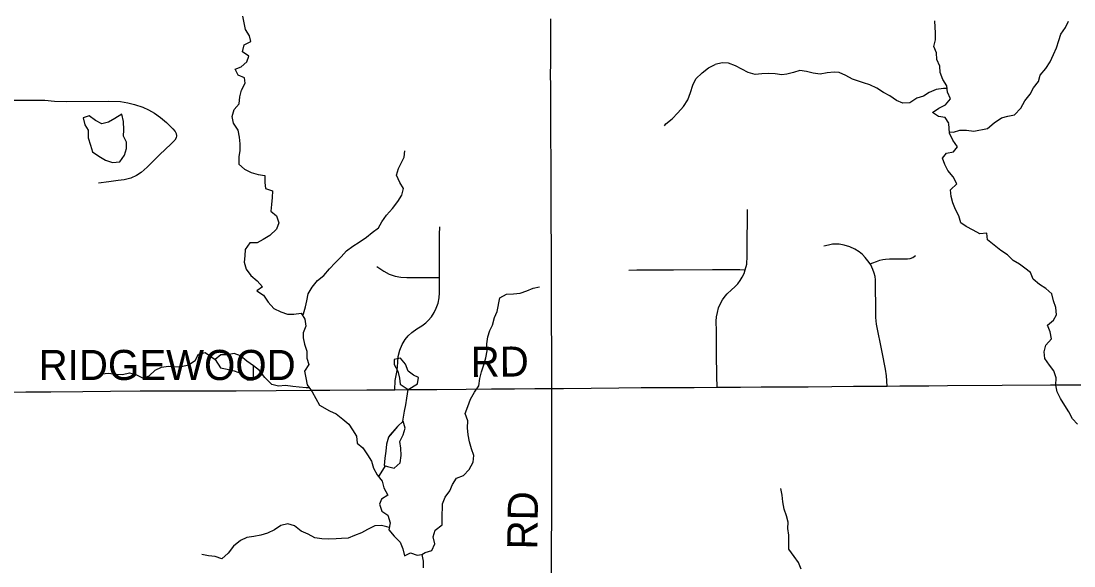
# Model space of a CAD drawing. Extents: x 0 to 34, y 0 to 22.
# Drawn here: x 6.998 to 7.992, y 14.845 to 15.36 of the extents above; entities that cross this region are included whole.
import ezdxf

# ---------------------------------------------------------------- set-up
doc = ezdxf.new("R2010")
doc.units = 0
for name, color, linetype in [('GM_X_County_Road', 7, 'Continuous'), ('GM_X_County_Road_Text', 7, 'Continuous'), ('GM_X_Minor_Lake', 7, 'Continuous'), ('GM_X_Minor_River', 7, 'Continuous'), ('GM_X_Township_Road', 7, 'Continuous'), ('GM_X_Township_Road_Text', 7, 'Continuous')]:
    doc.layers.add(name, color=color, linetype=linetype)

msp = doc.modelspace()

# ---------------------------------------------------------------- linework, layer by layer
at = {"layer": 'GM_X_County_Road'}
msp.add_lwpolyline([(6.98496, 15.00949), (7.00223, 15.00972), (7.02584, 15.00993), (7.05596, 15.01022), (7.08206, 15.0104), (7.11021, 15.01066), (7.20092, 15.01086), (7.23849, 15.01115), (7.27122, 15.01144), (7.28915, 15.01135), (7.32399, 15.01164), (7.3507, 15.01181), (7.36491, 15.01193), (7.39034, 15.01199), (7.41797, 15.01228), (7.44175, 15.0126), (7.46342, 15.0128), (7.48288, 15.01286), (7.4953, 15.01301), (7.49888, 15.01296), (7.50974, 15.01303), (7.536, 15.01332), (7.56212, 15.01352), (7.58306, 15.01376), (7.60788, 15.0139), (7.63299, 15.01405), (7.65484, 15.0142), (7.67693, 15.01437), (7.69654, 15.01457), (7.74068, 15.01468), (7.76315, 15.01483), (7.78369, 15.01503), (7.80642, 15.01518), (7.81548, 15.0152), (7.82718, 15.01534), (7.85482, 15.01561), (7.8722, 15.01579), (7.92384, 15.01606), (7.96966, 15.01632), (8.02509, 15.01647)], dxfattribs=at)
at = {"layer": 'GM_X_Minor_Lake'}
for points in [[(7.09463, 15.25704), (7.09448, 15.26508), (7.09285, 15.27188), (7.08629, 15.26797), (7.08012, 15.26445), (7.07409, 15.26283), (7.06798, 15.26595), (7.06205, 15.27021), (7.05621, 15.26859), (7.05784, 15.26178), (7.06104, 15.25679)], [(7.06104, 15.25679), (7.06094, 15.2559), (7.06116, 15.24945), (7.06327, 15.24282), (7.06519, 15.23639), (7.07126, 15.23243), (7.07752, 15.22848), (7.08416, 15.22623), (7.09097, 15.22683), (7.09549, 15.23329), (7.09717, 15.23956), (7.09714, 15.24544), (7.09428, 15.2513), (7.09463, 15.25705)], [(7.06104, 15.25679), (7.06094, 15.2559), (7.06116, 15.24945), (7.06327, 15.24282), (7.06519, 15.23639), (7.07126, 15.23243), (7.07752, 15.22848), (7.08416, 15.22623), (7.09097, 15.22683), (7.09549, 15.23329), (7.09717, 15.23956), (7.09714, 15.24544), (7.09428, 15.2513), (7.09463, 15.25704)], [(7.18087, 15.04041), (7.18587, 15.03254), (7.19235, 15.03114), (7.19901, 15.02975), (7.2057, 15.02702), (7.21112, 15.02124), (7.21719, 15.02117), (7.21712, 15.02887)], [(7.21712, 15.02887), (7.21714, 15.03426), (7.21079, 15.03888), (7.20482, 15.04389), (7.1989, 15.04606), (7.19247, 15.0448), (7.1864, 15.04488), (7.18089, 15.04039)], [(7.18089, 15.04039), (7.18587, 15.03254), (7.19235, 15.03114), (7.19901, 15.02975), (7.2057, 15.02702), (7.21112, 15.02124), (7.21719, 15.02117), (7.21712, 15.02887)], [(7.21723, 15.02887), (7.21714, 15.03426), (7.21079, 15.03888), (7.20482, 15.04389), (7.1989, 15.04606), (7.19247, 15.0448), (7.1864, 15.04488), (7.18092, 15.04041)], [(7.35272, 15.04093), (7.34978, 15.04034), (7.34987, 15.03559), (7.3534, 15.0294), (7.35504, 15.02279), (7.35553, 15.01691), (7.36321, 15.01213)], [(7.35272, 15.04093), (7.34978, 15.04034), (7.34987, 15.03559), (7.3534, 15.0294), (7.35504, 15.02279), (7.35553, 15.01691), (7.36322, 15.01212)], [(7.36321, 15.01213), (7.37202, 15.01722), (7.37305, 15.0235), (7.36827, 15.0255), (7.36307, 15.02939), (7.36049, 15.03598), (7.35602, 15.04159), (7.35272, 15.04093)], [(7.36323, 15.01214), (7.37202, 15.01722), (7.37305, 15.0235), (7.36827, 15.0255), (7.36307, 15.02939), (7.36049, 15.03598), (7.35602, 15.04159), (7.3528, 15.0409)], [(7.34038, 14.94023), (7.34351, 14.93946), (7.34999, 14.93769), (7.35558, 14.94292), (7.35659, 14.94977), (7.35608, 14.95659), (7.35521, 14.96302), (7.3585, 14.96934), (7.36028, 14.97564), (7.35827, 14.98205), (7.35323, 14.97721), (7.34605, 14.96901)], [(7.34038, 14.94023), (7.34351, 14.93946), (7.34999, 14.93769), (7.35558, 14.94292), (7.35659, 14.94977), (7.35608, 14.95659), (7.35521, 14.96302), (7.3585, 14.96934), (7.36028, 14.97564), (7.35827, 14.98205), (7.35323, 14.97721), (7.34599, 14.96894)], [(7.34605, 14.96901), (7.3447, 14.967), (7.34274, 14.96032), (7.3421, 14.95386), (7.34109, 14.9472), (7.34038, 14.94023)], [(7.34599, 14.96892), (7.3447, 14.967), (7.34274, 14.96032), (7.3421, 14.95386), (7.34109, 14.9472), (7.34038, 14.94022)]]:
    msp.add_lwpolyline(points, dxfattribs=at)
at = {"layer": 'GM_X_Minor_River'}
for points in [[(7.20187, 15.25785), (7.19815, 15.26329), (7.1969, 15.26972), (7.19887, 15.2764), (7.2035, 15.28179), (7.20414, 15.28844), (7.20592, 15.29473), (7.20921, 15.30105), (7.20874, 15.30636), (7.20265, 15.30872), (7.19971, 15.31436), (7.20553, 15.31674), (7.21075, 15.32138), (7.21273, 15.32673), (7.20661, 15.3308), (7.20838, 15.33747), (7.21476, 15.34043), (7.21334, 15.3459), (7.20945, 15.35191), (7.20821, 15.35815), (7.20696, 15.36458)], [(7.87372, 15.26329), (7.86996, 15.26888), (7.86387, 15.26982), (7.85816, 15.27343), (7.86424, 15.27762), (7.87033, 15.28067), (7.87507, 15.28657), (7.87221, 15.29284), (7.87163, 15.29873), (7.86801, 15.30462), (7.86553, 15.31128), (7.86495, 15.31736), (7.86227, 15.32363), (7.86188, 15.32972), (7.8594, 15.3358), (7.86111, 15.34227), (7.86091, 15.34835), (7.86047, 15.35996)], [(7.91631, 15.26364), (7.92323, 15.26837), (7.92913, 15.2699), (7.93559, 15.27124), (7.94148, 15.27753), (7.94528, 15.28437), (7.95021, 15.29085), (7.95344, 15.29675), (7.95819, 15.30265), (7.95989, 15.30873), (7.96502, 15.31501), (7.96919, 15.32148), (7.97223, 15.32833), (7.97526, 15.33461), (7.97734, 15.34146), (7.97924, 15.34755), (7.98379, 15.35364), (7.98664, 15.35973)], [(7.60501, 15.2609), (7.60648, 15.26285), (7.61226, 15.26769), (7.61784, 15.2731), (7.62322, 15.27927), (7.62727, 15.2856), (7.62979, 15.29247), (7.63175, 15.29934), (7.63487, 15.30527), (7.64063, 15.31088), (7.6466, 15.31573), (7.65297, 15.3188)], [(7.8719, 15.29602), (7.8684, 15.29626), (7.86156, 15.29511), (7.85509, 15.29225), (7.84958, 15.28901), (7.8433, 15.2871), (7.83665, 15.28253), (7.83018, 15.28233), (7.82409, 15.2848), (7.818, 15.28916), (7.81191, 15.29239), (7.80562, 15.29656), (7.79896, 15.2996), (7.79306, 15.30149), (7.7883, 15.303), (7.78259, 15.3049), (7.77631, 15.3085), (7.77003, 15.31135), (7.76527, 15.31153), (7.7588, 15.31095), (7.75196, 15.30961), (7.74549, 15.31056), (7.73921, 15.31226), (7.73293, 15.3132), (7.72703, 15.31129), (7.72057, 15.30957), (7.71581, 15.30919), (7.70972, 15.30994), (7.70364, 15.31031), (7.69717, 15.30993), (7.6907, 15.30935), (7.68423, 15.31124), (7.67814, 15.31447), (7.67204, 15.3175), (7.66557, 15.31997), (7.65948, 15.32053), (7.65297, 15.31877)], [(7.20186, 15.25786), (7.20236, 15.25688), (7.20371, 15.25025), (7.20431, 15.24381), (7.20414, 15.23774), (7.20322, 15.23167), (7.20325, 15.22485), (7.20876, 15.21994), (7.21483, 15.21693), (7.22165, 15.21488), (7.2279, 15.21396), (7.22774, 15.20732), (7.22852, 15.20164), (7.23497, 15.19958), (7.2348, 15.19313), (7.23426, 15.18668), (7.23353, 15.18042), (7.23885, 15.1759), (7.24115, 15.16946), (7.23871, 15.16338), (7.23249, 15.15748), (7.22626, 15.15347), (7.22059, 15.15041), (7.21377, 15.15057), (7.20926, 15.1443), (7.2089, 15.13823), (7.20836, 15.13235), (7.21028, 15.12572), (7.21466, 15.11948), (7.22055, 15.11458), (7.22549, 15.10891), (7.2204, 15.10529), (7.22647, 15.10095), (7.23104, 15.09434), (7.23618, 15.08848), (7.24301, 15.08529), (7.24926, 15.08323), (7.25532, 15.08307), (7.26213, 15.08404), (7.26556, 15.07837), (7.26654, 15.07193), (7.26391, 15.06566), (7.26412, 15.06073), (7.26528, 15.05486), (7.26758, 15.04805), (7.26742, 15.0416), (7.26952, 15.03554), (7.26519, 15.02927), (7.26655, 15.02302), (7.26771, 15.01657), (7.27266, 15.00996), (7.2759, 15.00353), (7.27952, 14.99729), (7.28901, 14.99202), (7.29508, 14.98901), (7.30154, 14.98392), (7.30705, 14.9792), (7.31048, 14.97391), (7.31429, 14.96786), (7.31489, 14.96123), (7.3202, 14.95689), (7.32477, 14.95046), (7.32858, 14.94441), (7.33031, 14.93778), (7.33394, 14.93154), (7.33869, 14.9255), (7.34005, 14.91906), (7.34386, 14.91225), (7.33782, 14.90862), (7.33594, 14.90368), (7.33824, 14.89725), (7.34394, 14.89329), (7.34624, 14.88628), (7.34475, 14.87945), (7.35008, 14.8736), (7.35559, 14.86793), (7.35808, 14.86169), (7.35962, 14.85506), (7.36548, 14.85774), (7.37173, 14.85549)], [(7.99518, 14.97919), (7.99037, 14.98446), (7.98688, 14.99089), (7.9832, 14.99694), (7.97914, 15.00355), (7.97584, 15.00979), (7.97462, 15.01625), (7.97493, 15.0231), (7.97258, 15.02954), (7.96852, 15.03501), (7.96408, 15.04143), (7.96344, 15.04751), (7.96508, 15.05381), (7.97053, 15.05977), (7.96912, 15.0666), (7.96658, 15.07266), (7.97242, 15.07749), (7.97521, 15.08266), (7.97457, 15.08931), (7.97241, 15.09575), (7.97081, 15.1022), (7.96524, 15.10747), (7.95912, 15.1112), (7.95317, 15.11608), (7.95082, 15.12253), (7.94526, 15.12646), (7.94028, 15.13021), (7.93416, 15.13375), (7.92897, 15.13902), (7.92265, 15.14333), (7.91651, 15.14839), (7.91018, 15.15327), (7.90935, 15.15973), (7.90289, 15.15909), (7.89639, 15.16244), (7.89008, 15.16598), (7.88491, 15.16935), (7.88294, 15.17598), (7.87983, 15.18204), (7.87748, 15.18829), (7.87589, 15.19436), (7.87525, 15.20044), (7.88108, 15.20621), (7.87778, 15.21265), (7.87258, 15.21868), (7.86966, 15.22435), (7.86751, 15.23041), (7.87144, 15.23522), (7.87789, 15.23624), (7.88164, 15.24104), (7.87739, 15.24746), (7.87409, 15.25389), (7.87367, 15.26327)], [(7.87401, 15.25514), (7.87787, 15.25508), (7.88394, 15.25686), (7.8904, 15.25693), (7.89725, 15.25587), (7.91015, 15.2583), (7.91633, 15.26364)], [(7.26307, 15.08249), (7.26441, 15.0833), (7.26627, 15.08994), (7.26739, 15.09582), (7.26887, 15.10227), (7.27244, 15.10855), (7.27753, 15.11482), (7.28338, 15.11959), (7.28884, 15.12587), (7.29412, 15.13158), (7.29997, 15.13729), (7.30506, 15.14281), (7.31091, 15.14739), (7.31695, 15.15102), (7.32375, 15.15597), (7.32922, 15.16017), (7.33526, 15.16455), (7.33826, 15.17044), (7.34278, 15.17653), (7.34825, 15.18281), (7.35352, 15.18947), (7.35709, 15.19555), (7.35877, 15.20162), (7.35534, 15.20749), (7.3521, 15.2143), (7.35415, 15.22057), (7.35697, 15.22645), (7.35922, 15.2312), (7.36014, 15.23746)], [(7.37608, 14.85627), (7.37929, 14.85813), (7.38554, 14.85993), (7.3883, 14.86643), (7.38688, 14.87287), (7.3885, 14.87917), (7.39509, 14.8842), (7.39538, 14.89029), (7.39557, 14.90397), (7.39814, 14.91028), (7.40243, 14.91623), (7.40501, 14.92235), (7.40892, 14.9283), (7.41535, 14.93086), (7.42059, 14.93664), (7.42449, 14.94354), (7.42516, 14.94982), (7.42298, 14.95606), (7.42099, 14.96249), (7.41994, 14.96931), (7.41927, 14.97595), (7.41956, 14.98242), (7.41699, 14.98922), (7.41937, 14.99609), (7.42212, 15.00298), (7.42564, 15.00949), (7.42993, 15.01563), (7.43079, 15.02229), (7.4324, 15.02878), (7.4346, 15.03527), (7.43659, 15.04195), (7.43783, 15.04843), (7.43754, 15.05526), (7.43821, 15.06173), (7.44022, 15.06784), (7.44262, 15.07282), (7.44461, 15.07988), (7.44719, 15.08562), (7.44967, 15.09857), (7.45609, 15.1019), (7.46256, 15.10218), (7.46902, 15.10285), (7.47507, 15.10522), (7.48112, 15.10778), (7.48719, 15.10881)], [(7.0738, 15.02674), (7.08024, 15.02733), (7.08725, 15.02642), (7.09349, 15.02625), (7.09993, 15.02761), (7.10656, 15.02574), (7.11282, 15.02273), (7.11868, 15.02484), (7.12434, 15.03037), (7.13038, 15.03324), (7.13682, 15.03402), (7.1425, 15.03348), (7.14931, 15.0337), (7.15574, 15.03543), (7.16197, 15.03944), (7.16517, 15.04552), (7.1716, 15.04687), (7.18087, 15.04044)], [(7.27, 15.01351), (7.26696, 15.01354), (7.26033, 15.01408), (7.25427, 15.01481), (7.24745, 15.01573), (7.24064, 15.01513), (7.23439, 15.01681), (7.22773, 15.02323), (7.22278, 15.03003), (7.21714, 15.03425)], [(7.35826, 14.982), (7.35982, 14.99156), (7.36093, 14.99764), (7.36185, 15.00371), (7.36324, 15.01214)], [(7.33464, 14.93065), (7.33621, 14.93098), (7.34165, 14.9399)], [(7.73422, 14.84247), (7.73149, 14.84872), (7.72743, 14.85438), (7.7226, 14.86137), (7.72253, 14.86822), (7.72265, 14.8745), (7.72163, 14.88095), (7.72175, 14.88666), (7.72035, 14.89274), (7.71819, 14.89918), (7.71698, 14.90583), (7.71633, 14.91229), (7.71512, 14.91855)], [(7.34525, 14.88176), (7.34285, 14.88229), (7.33811, 14.88378), (7.33167, 14.88338), (7.32487, 14.87975), (7.31901, 14.87669), (7.31259, 14.87419), (7.30635, 14.8717), (7.3001, 14.87149), (7.29518, 14.87109), (7.28818, 14.87087), (7.28155, 14.87103), (7.27511, 14.87214), (7.26885, 14.87552), (7.26221, 14.87834), (7.25594, 14.88343), (7.24969, 14.88511), (7.24288, 14.88356), (7.23684, 14.87956), (7.23023, 14.8765), (7.22399, 14.87438), (7.21755, 14.87322), (7.21093, 14.87243), (7.2047, 14.86956), (7.19828, 14.86403), (7.1932, 14.85757), (7.18716, 14.85204), (7.18109, 14.85448), (7.17465, 14.85502), (7.1684, 14.85613)], [(7.37173, 14.85549), (7.37608, 14.85627), (7.37743, 14.85002), (7.37727, 14.84357)]]:
    msp.add_lwpolyline(points, dxfattribs=at)
at = {"layer": 'GM_X_Township_Road'}
for points in [[(7.49849, 14.83606), (7.49856, 14.85497), (7.4986, 14.86661), (7.49865, 14.89008), (7.49881, 14.96622), (7.49888, 15.01296), (7.49871, 15.0561), (7.49857, 15.06951), (7.49848, 15.11647), (7.49844, 15.12605), (7.4984, 15.13545), (7.49837, 15.14473), (7.49833, 15.15409), (7.4983, 15.1637), (7.49826, 15.17311), (7.49817, 15.1963), (7.4981, 15.21388), (7.49803, 15.23283), (7.49798, 15.24558), (7.49791, 15.25973), (7.49781, 15.28033), (7.49772, 15.29928), (7.49767, 15.30834), (7.49776, 15.3206), (7.49772, 15.36183)], [(6.99007, 15.28512), (7.00478, 15.28531), (7.02005, 15.28518), (7.02938, 15.28433), (7.04046, 15.28394), (7.08024, 15.28429), (7.09159, 15.28382), (7.09855, 15.28261), (7.10481, 15.28114), (7.11251, 15.27845), (7.1181, 15.27597), (7.12355, 15.27286), (7.12938, 15.26885), (7.1349, 15.26403), (7.14096, 15.25816), (7.14322, 15.25563), (7.14403, 15.25373), (7.14446, 15.25159), (7.14411, 15.24961), (7.14295, 15.24731), (7.13933, 15.24382), (7.12848, 15.23343), (7.1167, 15.22177), (7.11118, 15.21699), (7.10675, 15.21407), (7.10139, 15.21143), (7.09517, 15.20999), (7.08941, 15.20925), (7.08059, 15.20808), (7.07068, 15.20683)], [(7.65484, 15.0142), (7.65468, 15.0246), (7.65435, 15.04557), (7.65421, 15.06722), (7.65405, 15.07645), (7.65432, 15.08077), (7.65506, 15.08475), (7.65621, 15.08901), (7.65763, 15.09262), (7.65987, 15.0968), (7.6623, 15.10013), (7.66421, 15.10226), (7.66825, 15.10605), (7.67155, 15.10887), (7.67431, 15.11168), (7.67669, 15.11485), (7.67852, 15.11793), (7.68026, 15.12165), (7.68141, 15.12505), (7.68275, 15.1303), (7.68332, 15.13784), (7.68327, 15.1522), (7.68335, 15.1739), (7.68344, 15.18194)], [(7.3507, 15.01181), (7.35088, 15.0204), (7.35211, 15.02665), (7.35284, 15.03002), (7.35347, 15.03755), (7.35381, 15.04318), (7.35529, 15.04908), (7.35758, 15.0545), (7.36033, 15.05916), (7.36307, 15.06268), (7.36663, 15.0658), (7.37117, 15.0692), (7.37605, 15.07216), (7.37992, 15.075), (7.38203, 15.07725), (7.38502, 15.08063), (7.38766, 15.08464), (7.38966, 15.08885), (7.39132, 15.09361), (7.39227, 15.09851), (7.39266, 15.10321), (7.39276, 15.11372), (7.3928, 15.11773), (7.39288, 15.15837), (7.39296, 15.16554)], [(7.81548, 15.0152), (7.81482, 15.02476), (7.81363, 15.03134), (7.81051, 15.04733), (7.80541, 15.07362), (7.80463, 15.07985), (7.80454, 15.08906), (7.80445, 15.10951), (7.80419, 15.11553), (7.8039, 15.11863), (7.80295, 15.12176), (7.80178, 15.12525), (7.79983, 15.12977), (7.79943, 15.1306), (7.79714, 15.13362), (7.79462, 15.13676), (7.79217, 15.13939), (7.78877, 15.14206), (7.78487, 15.14444), (7.78012, 15.14677), (7.77463, 15.14842), (7.77, 15.14915), (7.7664, 15.14925), (7.7638, 15.14913), (7.76009, 15.14831), (7.75546, 15.14721)], [(7.79943, 15.1306), (7.8017, 15.13151), (7.80532, 15.13297), (7.80858, 15.13413), (7.81139, 15.13475), (7.81362, 15.13505), (7.81744, 15.13526), (7.82827, 15.13522), (7.83463, 15.13535), (7.83695, 15.13573), (7.83964, 15.13677), (7.84225, 15.13867)], [(7.3336, 15.12815), (7.34006, 15.1237), (7.34513, 15.12095), (7.35073, 15.11898), (7.35624, 15.11793), (7.36204, 15.11767), (7.3928, 15.11773)], [(7.57131, 15.12468), (7.57912, 15.12492), (7.6135, 15.12487), (7.65047, 15.12544), (7.67636, 15.12528), (7.68141, 15.12505)]]:
    msp.add_lwpolyline(points, dxfattribs=at)

# ---------------------------------------------------------------- texts
at = {"layer": 'GM_X_County_Road_Text'}
for s, rotation, p in [('RIDGEWOOD', 359.99915, (7.01428, 15.02098)), ('RD', 0.49364, (7.42227, 15.02388))]:
    msp.add_text(s, height=0.028409, rotation=rotation, dxfattribs=at).set_placement(p)
at = {"layer": 'GM_X_Township_Road_Text'}
msp.add_text('RD', height=0.028409, rotation=89.0109, dxfattribs=at).set_placement((7.48494, 14.86082))

doc.saveas('drawing.dxf')
